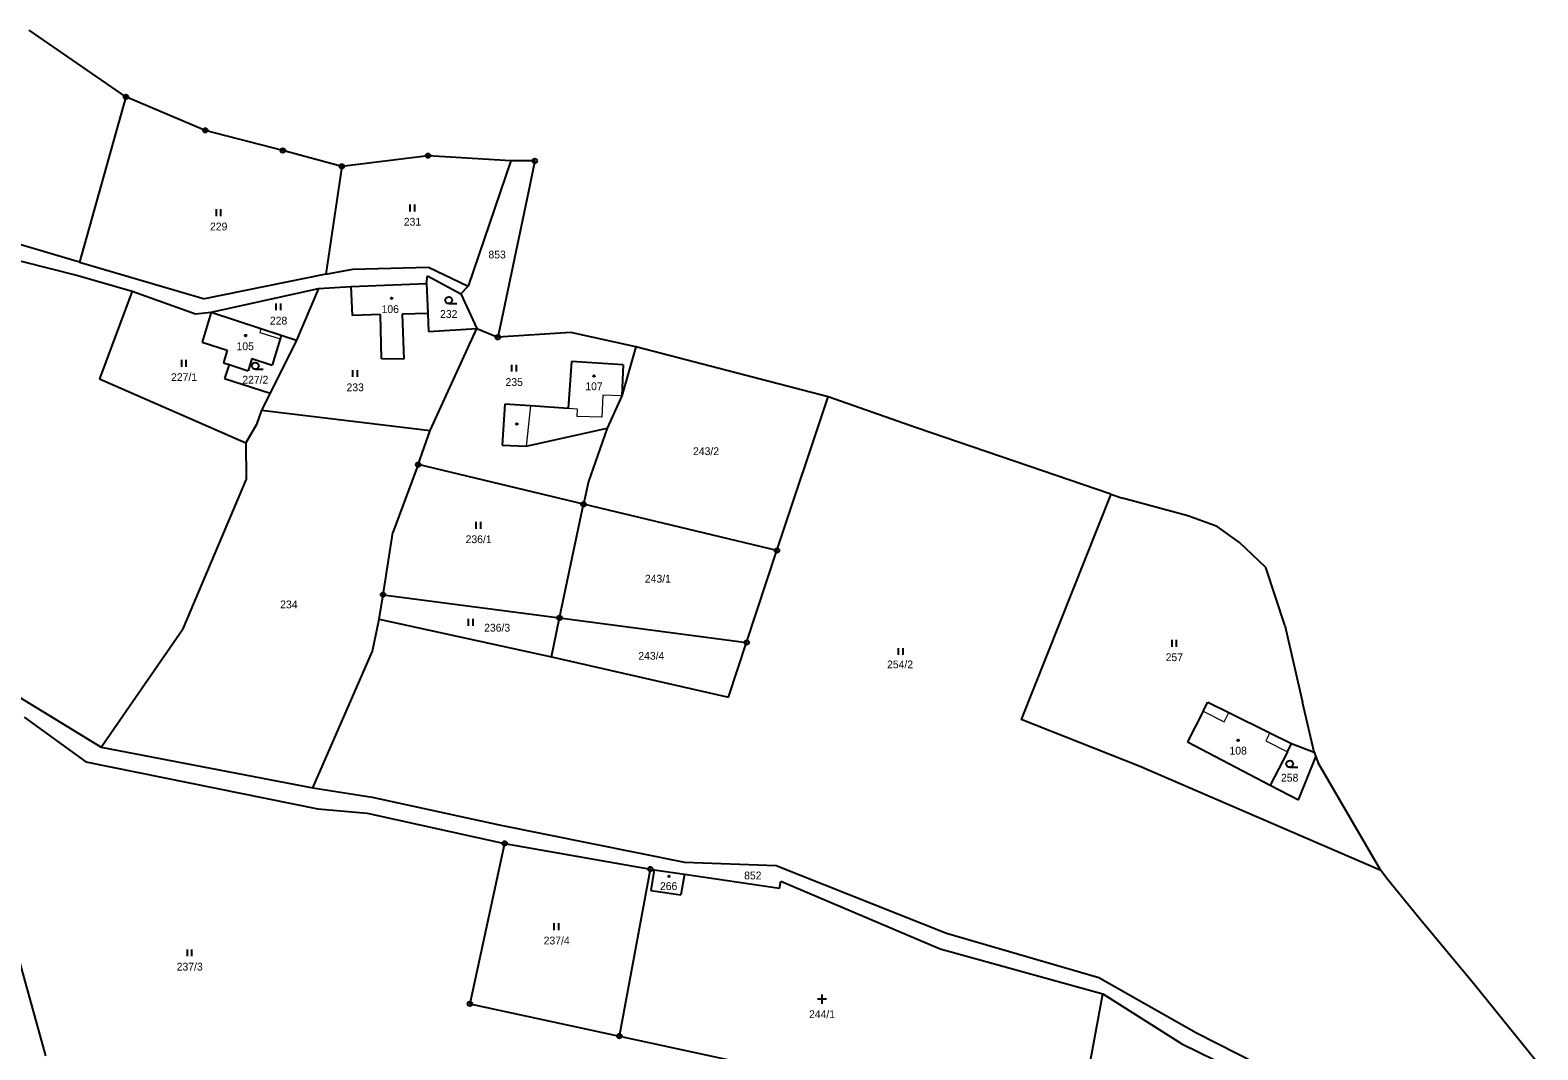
# Model space of a CAD drawing. Extents: x -739410 to -735662, y -942282 to -940043.
# Drawn here: x -737454.1 to -737124.5, y -940819.5 to -940596.6 of the extents above; entities that cross this region are included whole.
import ezdxf
from ezdxf.enums import TextEntityAlignment as Align

# ---------------------------------------------------------------- set-up
doc = ezdxf.new("R2010")
doc.units = 0
doc.header["$LTSCALE"] = 0.68
for name, color, linetype, lineweight in [('1', 7, 'Continuous', 25), ('3', 7, 'Continuous', 25), ('4', 7, 'Continuous', 13), ('5', 7, 'Continuous', 25), ('8', 7, 'Continuous', 25)]:
    doc.layers.add(name, color=color, linetype=linetype, lineweight=lineweight)
doc.layers.add('2', color=7, linetype='Continuous')

msp = doc.modelspace()

# ---------------------------------------------------------------- linework, layer by layer
at = {"layer": '1'}
for p, q in [((-737433.14, -940611.23), (-737454.28, -940596.64)), ((-737433.14, -940611.23), (-737443.31, -940647.36)), ((-737415.8, -940618.54), (-737433.14, -940611.23)), ((-737398.86, -940622.95), (-737415.8, -940618.54)), ((-737385.95, -940626.41), (-737398.86, -940622.95)), ((-737385.95, -940626.41), (-737389.45, -940649.98)), ((-737367.1, -940624.08), (-737385.95, -940626.41)), ((-737349.03, -940625.24), (-737367.1, -940624.08)), ((-737349.03, -940625.24), (-737358.35, -940652.6)), ((-737343.75, -940625.23), (-737349.03, -940625.24)), ((-737343.75, -940625.23), (-737345.23, -940632.26)), ((-737345.23, -940632.26), (-737351.28, -940661.09)), ((-737443.31, -940647.36), (-737466.56, -940640.53)), ((-737467.44, -940644.28), (-737443.67, -940650.24)), ((-737443.31, -940647.36), (-737415.98, -940655.35)), ((-737389.45, -940649.98), (-737383.57, -940648.87)), ((-737383.57, -940648.87), (-737367.02, -940648.46)), ((-737367.02, -940648.46), (-737358.35, -940652.6)), ((-737443.67, -940650.24), (-737431.81, -940653.72)), ((-737389.45, -940649.98), (-737415.98, -940655.35)), ((-737391.04, -940653.11), (-737383.88, -940652.67)), ((-737383.88, -940652.67), (-737367.41, -940652.05)), ((-737383.6, -940659), (-737383.88, -940652.67)), ((-737367.41, -940652.05), (-737367.22, -940650.31)), ((-737367.41, -940652.05), (-737367.13, -940658.57)), ((-737367.22, -940650.31), (-737359.96, -940654.25)), ((-737359.96, -940654.25), (-737358.35, -940652.6)), ((-737431.81, -940653.72), (-737438.95, -940672.83)), ((-737431.81, -940653.72), (-737417.92, -940658.67)), ((-737414.48, -940658.31), (-737391.04, -940653.11)), ((-737391.04, -940653.11), (-737395.85, -940664.43)), ((-737359.96, -940654.25), (-737356.43, -940661.85)), ((-737417.92, -940658.67), (-737414.48, -940658.31)), ((-737414.48, -940658.31), (-737416.45, -940664.81)), ((-737414.48, -940658.31), (-737403.65, -940661.88)), ((-737377.52, -940658.8), (-737383.6, -940659)), ((-737377.31, -940668.5), (-737377.52, -940658.8)), ((-737367.13, -940658.57), (-737372.73, -940658.69)), ((-737372.73, -940658.69), (-737372.42, -940668.57)), ((-737367.13, -940658.57), (-737367.03, -940662.51)), ((-737403.65, -940661.88), (-737399.19, -940663.34)), ((-737367.03, -940662.51), (-737356.43, -940661.85)), ((-737366.63, -940684.15), (-737356.43, -940661.85)), ((-737356.43, -940661.85), (-737351.84, -940663.77)), ((-737351.28, -940661.09), (-737351.84, -940663.77)), ((-737335.89, -940662.75), (-737351.84, -940663.77)), ((-737321.69, -940665.86), (-737335.89, -940662.75)), ((-737416.45, -940664.81), (-737411, -940666.61)), ((-737395.85, -940664.43), (-737401.61, -940675.97)), ((-737399.42, -940664.11), (-737401.16, -940669.85)), ((-737399.19, -940663.34), (-737399.42, -940664.11)), ((-737399.19, -940663.34), (-737395.85, -940664.43)), ((-737321.69, -940665.86), (-737324.72, -940676.55)), ((-737279.65, -940676.77), (-737321.69, -940665.86)), ((-737411, -940666.61), (-737411.83, -940669.34)), ((-737411.83, -940669.34), (-737410.6, -940669.75)), ((-737405.59, -940668.39), (-737406.42, -940671.13)), ((-737405.59, -940668.39), (-737401.16, -940669.85)), ((-737372.42, -940668.57), (-737377.31, -940668.5)), ((-737335.73, -940669.08), (-737336.49, -940679.32)), ((-737324.42, -940669.83), (-737335.73, -940669.08)), ((-737438.95, -940672.83), (-737406.97, -940686.87)), ((-737410.6, -940669.75), (-737411.58, -940672.76)), ((-737411.58, -940672.76), (-737401.61, -940675.97)), ((-737410.6, -940669.75), (-737406.42, -940671.13)), ((-737324.42, -940669.83), (-737324.72, -940676.55)), ((-737401.61, -940675.97), (-737403.48, -940679.71)), ((-737350.33, -940678.37), (-737350.9, -940687.35)), ((-737344.7, -940678.73), (-737350.33, -940678.37)), ((-737336.49, -940679.32), (-737344.7, -940678.73)), ((-737324.72, -940676.55), (-737327.93, -940683.67)), ((-737290.82, -940710.38), (-737279.65, -940676.77)), ((-737260.31, -940683.58), (-737279.65, -940676.77)), ((-737403.48, -940679.71), (-737404.62, -940682.81)), ((-737403.48, -940679.71), (-737366.63, -940684.15)), ((-737404.62, -940682.81), (-737406.97, -940686.87)), ((-737369.27, -940691.62), (-737366.63, -940684.15)), ((-737345.62, -940687.6), (-737327.93, -940683.67)), ((-737327.93, -940683.67), (-737332.04, -940695.31)), ((-737241.92, -940689.84), (-737260.31, -940683.58)), ((-737406.97, -940686.87), (-737406.86, -940694.8)), ((-737350.9, -940687.35), (-737345.62, -940687.6)), ((-737369.27, -940691.62), (-737374.79, -940706.44)), ((-737333.13, -940700.29), (-737369.27, -940691.62)), ((-737217.83, -940698.09), (-737241.92, -940689.84)), ((-737406.86, -940694.8), (-737420.75, -940727.69)), ((-737332.04, -940695.31), (-737333.13, -940700.29)), ((-737217.83, -940698.09), (-737237.43, -940747.35)), ((-737217.83, -940698.09), (-737215.29, -940698.96)), ((-737200.96, -940702.81), (-737215.29, -940698.96)), ((-737338.35, -940725.12), (-737333.13, -940700.29)), ((-737290.82, -940710.38), (-737333.13, -940700.29)), ((-737194.59, -940705.14), (-737200.96, -940702.81)), ((-737189.68, -940708.62), (-737194.59, -940705.14)), ((-737376.94, -940720.05), (-737374.79, -940706.44)), ((-737183.97, -940714.09), (-737189.68, -940708.62)), ((-737297.45, -940730.49), (-737290.82, -940710.38)), ((-737179.82, -940726.73), (-737183.97, -940714.09)), ((-737377.79, -940725.4), (-737376.94, -940720.05)), ((-737376.94, -940720.05), (-737338.35, -940725.12)), ((-737379.22, -940732.41), (-737377.79, -940725.4)), ((-737377.79, -940725.4), (-737340.14, -940733.63)), ((-737340.14, -940733.63), (-737338.35, -940725.12)), ((-737338.35, -940725.12), (-737297.45, -940730.49)), ((-737438.56, -940753.35), (-737420.75, -940727.69)), ((-737179.82, -940726.73), (-737175.93, -940743.57)), ((-737301.41, -940742.48), (-737297.45, -940730.49)), ((-737469.27, -940734.66), (-737438.56, -940753.35)), ((-737392.26, -940762.3), (-737379.22, -940732.41)), ((-737340.14, -940733.63), (-737301.41, -940742.48)), ((-737197.61, -940745.54), (-737196.63, -940743.55)), ((-737196.63, -940743.55), (-737192.06, -940745.81)), ((-737173.38, -940754.46), (-737175.93, -940743.57)), ((-737455.38, -940746.82), (-737441.92, -940756.57)), ((-737211.61, -940757.51), (-737237.43, -940747.35)), ((-737197.61, -940745.54), (-737201.1, -940752.23)), ((-737192.06, -940745.81), (-737183.1, -940750.24)), ((-737183.1, -940750.24), (-737178.33, -940752.6)), ((-737438.56, -940753.35), (-737392.26, -940762.3)), ((-737201.1, -940752.23), (-737182.99, -940761.67)), ((-737179.23, -940754.43), (-737182.99, -940761.67)), ((-737179.23, -940754.43), (-737178.33, -940752.6)), ((-737178.33, -940752.6), (-737173.38, -940754.46)), ((-737173.38, -940754.46), (-737172.99, -940755.52)), ((-737441.92, -940756.57), (-737391.19, -940766.85)), ((-737158.78, -940780.3), (-737211.61, -940757.51)), ((-737176.83, -940764.9), (-737172.99, -940755.52)), ((-737172.99, -940755.52), (-737172.5, -940756.83)), ((-737165.52, -940768.85), (-737172.5, -940756.83)), ((-737182.99, -940761.67), (-737176.83, -940764.9)), ((-737392.26, -940762.3), (-737379.29, -940764.27)), ((-737379.29, -940764.27), (-737351.53, -940770.36)), ((-737391.19, -940766.85), (-737380.41, -940767.79)), ((-737380.41, -940767.79), (-737350.36, -940774.41)), ((-737351.53, -940770.36), (-737311.01, -940778.52)), ((-737158.78, -940780.3), (-737165.52, -940768.85)), ((-737350.36, -940774.41), (-737357.97, -940809.47)), ((-737350.36, -940774.41), (-737318.5, -940780.03)), ((-737325.27, -940816.53), (-737318.5, -940780.03)), ((-737318.5, -940780.03), (-737317.63, -940780.18)), ((-737317.63, -940780.18), (-737318.42, -940784.68)), ((-737317.63, -940780.18), (-737311.04, -940781.14)), ((-737311.04, -940781.14), (-737311.83, -940785.64)), ((-737311.04, -940781.14), (-737290.24, -940784.2)), ((-737311.01, -940778.52), (-737290.98, -940779.23)), ((-737290.98, -940779.23), (-737253.78, -940794.06)), ((-737157.22, -940782.43), (-737158.78, -940780.3)), ((-737318.42, -940784.68), (-737311.83, -940785.64)), ((-737290.24, -940784.2), (-737289.98, -940782.65)), ((-737289.98, -940782.65), (-737255.17, -940797.48)), ((-737150.4, -940790.77), (-737157.22, -940782.43)), ((-737138.52, -940805.04), (-737150.4, -940790.77)), ((-737458.33, -940793.46), (-737450.75, -940820.84)), ((-737253.78, -940794.06), (-737220.45, -940803.7)), ((-737255.17, -940797.48), (-737219.58, -940807.28)), ((-737220.45, -940803.7), (-737199.07, -940815.84)), ((-737223.34, -940827.69), (-737219.58, -940807.28)), ((-737219.58, -940807.28), (-737202.33, -940818.24)), ((-737124.47, -940822.45), (-737138.52, -940805.04)), ((-737357.97, -940809.47), (-737325.27, -940816.53)), ((-737325.27, -940816.53), (-737262.57, -940830.05)), ((-737199.07, -940815.84), (-737163.14, -940834.03)), ((-737202.33, -940818.24), (-737167.43, -940835.21))]:
    msp.add_line(p, q, dxfattribs=at)
at = {"layer": '3'}
for p, q in [((-737413.381, -940637.28), (-737413.381, -940635.78)), ((-737412.38, -940637.28), (-737412.38, -940635.78)), ((-737371.021, -940636.25), (-737371.021, -940634.75)), ((-737370.02, -940636.25), (-737370.02, -940634.75)), ((-737400.291, -940657.86), (-737400.291, -940656.36)), ((-737399.29, -940657.86), (-737399.29, -940656.36)), ((-737362.573, -940656.42), (-737360.823, -940656.42)), ((-737420.951, -940670.21), (-737420.951, -940668.71)), ((-737419.95, -940670.21), (-737419.95, -940668.71)), ((-737404.863, -940670.78), (-737403.113, -940670.78)), ((-737383.541, -940672.44), (-737383.541, -940670.94)), ((-737382.54, -940672.44), (-737382.54, -940670.94)), ((-737348.781, -940671.29), (-737348.781, -940669.79)), ((-737347.78, -940671.29), (-737347.78, -940669.79)), ((-737356.551, -940705.65), (-737356.551, -940704.15)), ((-737355.55, -940705.65), (-737355.55, -940704.15)), ((-737358.251, -940726.84), (-737358.251, -940725.34)), ((-737357.25, -940726.84), (-737357.25, -940725.34)), ((-737264.211, -940733.22), (-737264.211, -940731.72)), ((-737263.21, -940733.22), (-737263.21, -940731.72)), ((-737204.451, -940731.44), (-737204.451, -940729.94)), ((-737203.45, -940731.44), (-737203.45, -940729.94)), ((-737178.723, -940757.78), (-737176.973, -940757.78)), ((-737339.491, -940793.37), (-737339.491, -940791.87)), ((-737338.49, -940793.37), (-737338.49, -940791.87)), ((-737419.721, -940799.08), (-737419.721, -940797.58)), ((-737418.72, -940799.08), (-737418.72, -940797.58)), ((-737280.96, -940809.47), (-737280.96, -940807.47)), ((-737279.959, -940808.471), (-737281.961, -940808.471))]:
    msp.add_line(p, q, dxfattribs=at)
for centre in [(-737362.5729, -940655.6698), (-737404.8629, -940670.0298), (-737178.7229, -940757.0298)]:
    msp.add_circle(centre, 0.75, dxfattribs=at)
at = {"layer": '4'}
for p, q in [((-737403.65, -940661.88), (-737403.91, -940662.72)), ((-737403.91, -940662.72), (-737399.42, -940664.11)), ((-737344.7, -940678.73), (-737345.62, -940687.6)), ((-737328.89, -940676.43), (-737329.09, -940681.25)), ((-737324.72, -940676.55), (-737328.89, -940676.43)), ((-737329.09, -940681.25), (-737334.47, -940681.08)), ((-737197.61, -940745.54), (-737193.07, -940747.87)), ((-737193.07, -940747.87), (-737192.06, -940745.81)), ((-737183.1, -940750.24), (-737183.97, -940752)), ((-737183.97, -940752), (-737179.23, -940754.43))]:
    msp.add_line(p, q, dxfattribs=at)
msp.add_lwpolyline([(-737334.47, -940681.08), (-737334.42, -940679.47), (-737336.49, -940679.32)], dxfattribs=at)
at = {"layer": '5'}
for centre in [(-737375.0668, -940655.2792), (-737406.9568, -940663.3992), (-737330.8268, -940672.2192), (-737347.6868, -940682.7292), (-737189.9968, -940751.8692), (-737314.4068, -940781.6092)]:
    msp.add_circle(centre, 0.175, dxfattribs=at)
at = {"layer": '8'}
for centre, radius in [((-737433.14, -940611.2299), 0.5), ((-737433.14, -940611.2299), 0.0303), ((-737415.8, -940618.5399), 0.5), ((-737415.8, -940618.5399), 0.0303), ((-737398.86, -940622.9499), 0.5), ((-737398.86, -940622.9499), 0.0303), ((-737385.95, -940626.4099), 0.5), ((-737385.95, -940626.4099), 0.0303), ((-737367.1, -940624.0799), 0.5), ((-737367.1, -940624.0799), 0.0303), ((-737343.75, -940625.2299), 0.5), ((-737343.75, -940625.2299), 0.0303), ((-737351.84, -940663.7699), 0.5), ((-737351.84, -940663.7699), 0.0303), ((-737369.27, -940691.6199), 0.5), ((-737369.27, -940691.6199), 0.0303), ((-737333.13, -940700.2899), 0.5), ((-737333.13, -940700.2899), 0.0303), ((-737290.82, -940710.3799), 0.5), ((-737290.82, -940710.3799), 0.0303), ((-737376.94, -940720.0499), 0.5), ((-737376.94, -940720.0499), 0.0303), ((-737338.35, -940725.1199), 0.5), ((-737338.35, -940725.1199), 0.0303), ((-737297.45, -940730.4899), 0.5), ((-737297.45, -940730.4899), 0.0303), ((-737350.36, -940774.4099), 0.5), ((-737350.36, -940774.4099), 0.0303), ((-737318.5, -940780.0299), 0.5), ((-737318.5, -940780.0299), 0.0303), ((-737357.97, -940809.4699), 0.5), ((-737357.97, -940809.4699), 0.0303), ((-737325.27, -940816.5299), 0.5), ((-737325.27, -940816.5299), 0.0303)]:
    msp.add_circle(centre, radius, dxfattribs=at)

# ---------------------------------------------------------------- texts
at = {"layer": '2'}
for s, p in [('229', (-737412.869, -940640.405)), ('231', (-737370.509, -940639.375)), ('853', (-737351.999, -940646.545)), ('228', (-737399.779, -940660.985)), ('106', (-737375.359, -940658.475)), ('232', (-737362.579, -940659.545)), ('105', (-737407.069, -940666.595)), ('227/1', (-737420.44, -940673.335)), ('227/2', (-737404.87, -940673.905)), ('235', (-737348.269, -940674.415)), ('233', (-737383.029, -940675.565)), ('107', (-737330.819, -940675.345)), ('243/2', (-737306.32, -940689.525)), ('236/1', (-737356.04, -940708.775)), ('243/1', (-737316.85, -940717.395)), ('234', (-737397.529, -940723.025)), ('236/3', (-737351.99, -940728.115)), ('243/4', (-737318.28, -940734.255)), ('254/2', (-737263.9, -940736.135)), ('257', (-737203.939, -940734.565)), ('108', (-737189.989, -940754.995)), ('258', (-737178.729, -940760.905)), ('852', (-737296.099, -940782.275)), ('266', (-737314.499, -940784.605)), ('237/4', (-737338.98, -940796.495)), ('237/3', (-737419.21, -940802.205)), ('244/1', (-737280.96, -940812.595))]:
    msp.add_text(s, height=1.7, dxfattribs=at).set_placement(p, align=Align.CENTER)

doc.saveas('drawing.dxf')
